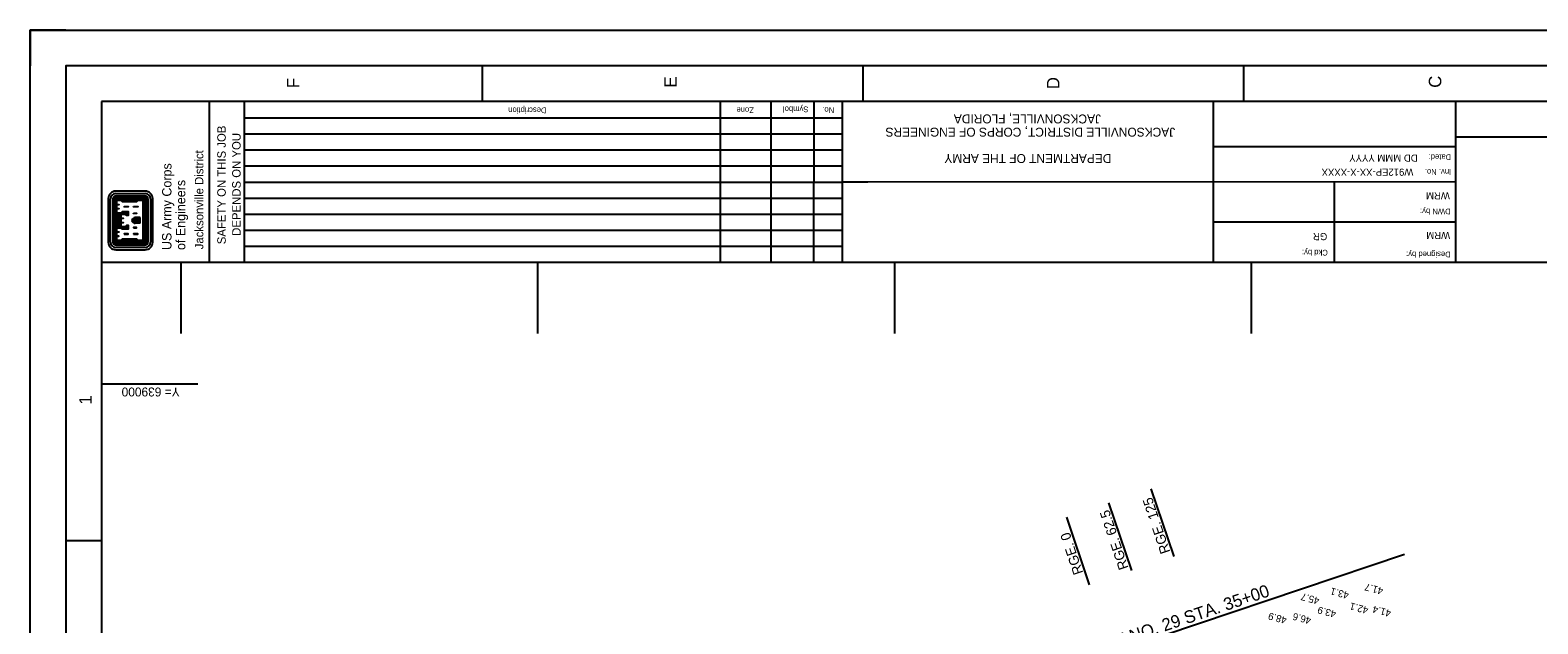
# Model space of a CAD drawing. Extents: x 945289 to 948688, y 635096 to 639496.
# Drawn here: x 945289 to 947401, y 638664 to 639496 of the extents above; entities that cross this region are included whole.
import ezdxf

# ---------------------------------------------------------------- set-up
doc = ezdxf.new("R2010")
doc.units = 0
for name, color, linetype in [('G-ANNO-NPLT', 7, 'Continuous'), ('G-ANNO-TEXT-DRWG', 7, 'Continuous'), ('G-ANNO-TEXT-LOGO', 7, 'Continuous'), ('G-ANNO-TEXT-PROJ', 7, 'Continuous'), ('G-ANNO-TEXT-TTLB', 7, 'Continuous'), ('G-ANNO-TTLB', 7, 'Continuous'), ('V-ALGN-TEXT', 7, 'Continuous'), ('V-ANNO-MATC', 7, 'Continuous'), ('V-ANNO-MATC-IDEN', 7, 'Continuous'), ('V-TOPO-COOR-STAT', 7, 'Continuous'), ('V-TOPO-SOUN', 7, 'Continuous')]:
    doc.layers.add(name, color=color, linetype=linetype)

msp = doc.modelspace()

# ---------------------------------------------------------------- linework, layer by layer
at = {"layer": 'G-ANNO-NPLT'}
msp.add_lwpolyline([(945288.5, 635095.9), (945288.5, 639495.8), (948688.5, 639495.8), (948688.5, 635095.9)], close=True, dxfattribs=at)
msp.add_lwpolyline([(945338.5, 639495.8), (945288.5, 639495.8), (945288.5, 639445.8)], dxfattribs=at)
at = {"layer": 'G-ANNO-TEXT-LOGO'}
for p, q in [((945397.9, 639259.7), (945397.9, 639198.9)), ((945401.1, 639198.9), (945401.1, 639259.7)), ((945404.5, 639259.7), (945404.5, 639198.9)), ((945405.4, 639259.7), (945405.4, 639198.9)), ((945406.3, 639259.7), (945406.3, 639198.9)), ((945407.1, 639259.7), (945407.1, 639198.9)), ((945408, 639259.7), (945408, 639198.9)), ((945449.6, 639270.4), (945408.6, 639270.4)), ((945408.6, 639267.1), (945449.6, 639267.1)), ((945408.6, 639263.7), (945449.6, 639263.7)), ((945408.6, 639262.8), (945449.6, 639262.8)), ((945408.6, 639261.9), (945449.6, 639261.9)), ((945408.6, 639261.1), (945449.6, 639261.1)), ((945408.6, 639260.2), (945449.6, 639260.2)), ((945408.6, 639259.3), (945449.3, 639259.3)), ((945408.6, 639258.5), (945448.4, 639258.5)), ((945417.4, 639257.8), (945438.2, 639257.8)), ((945418.2, 639256.9), (945437.3, 639256.9)), ((945448.4, 639258.5), (945448.4, 639200.1)), ((945449.3, 639259.3), (945449.3, 639199.3)), ((945450.2, 639259.7), (945450.2, 639198.9)), ((945451, 639259.7), (945451, 639198.9)), ((945451.9, 639259.7), (945451.9, 639198.9)), ((945452.8, 639259.7), (945452.8, 639198.9)), ((945453.6, 639259.7), (945453.6, 639198.9)), ((945457.1, 639259.7), (945457.1, 639198.9)), ((945460.4, 639198.9), (945460.4, 639259.7)), ((945408.8, 639220), (945408.8, 639238.6)), ((945409.7, 639220), (945409.7, 639238.6)), ((945410.5, 639220), (945410.5, 639238.6)), ((945411.4, 639220), (945411.4, 639238.6)), ((945412.3, 639220), (945412.3, 639238.6)), ((945413.1, 639220), (945413.1, 639238.6)), ((945414, 639220), (945414, 639238.6)), ((945442.5, 639233.3), (945435.8, 639233.3)), ((945442.5, 639232.5), (945435.8, 639232.5)), ((945442.5, 639231.6), (945435.8, 639231.6)), ((945442.5, 639230.7), (945435.8, 639230.7)), ((945442.5, 639229.9), (945435.8, 639229.9)), ((945442.5, 639228.7), (945435.8, 639228.7)), ((945442.5, 639227.9), (945435.8, 639227.9)), ((945442.5, 639227), (945435.8, 639227)), ((945442.5, 639226.1), (945435.8, 639226.1)), ((945442.5, 639225.3), (945435.8, 639225.3)), ((945442.5, 639225.3), (945442.5, 639233.3)), ((945408.6, 639200.1), (945448.4, 639200.1)), ((945408.6, 639199.3), (945449.3, 639199.3)), ((945408.6, 639198.4), (945449.6, 639198.4)), ((945408.6, 639197.5), (945449.6, 639197.5)), ((945408.6, 639196.6), (945449.6, 639196.6)), ((945408.6, 639195.8), (945449.6, 639195.8)), ((945408.6, 639194.9), (945449.6, 639194.9)), ((945417.3, 639200.8), (945438.3, 639200.8)), ((945418.2, 639201.7), (945437.3, 639201.7)), ((945449.6, 639191.4), (945408.6, 639191.4)), ((945408.6, 639188.2), (945449.6, 639188.2))]:
    msp.add_line(p, q, dxfattribs=at)
for points in [[(945408.6, 639200.8), (945416.5, 639200.8), (945418.2, 639202.5), (945437.3, 639202.5), (945439.1, 639200.8), (945447.8, 639200.8), (945447.8, 639257.8), (945439.1, 639257.8), (945437.3, 639256), (945418.2, 639256), (945416.5, 639257.8), (945408.6, 639257.8), (945408.6, 639250.3), (945408.6, 639244.5), (945408.6, 639239.1), (945416.5, 639239.1), (945418.2, 639241), (945425.2, 639241), (945425.2, 639236.8), (945424.5, 639236.8), (945422.7, 639238.6), (945414.9, 639238.6), (945414.9, 639231.1), (945414.9, 639225.3), (945414.9, 639220), (945422.7, 639220), (945424.5, 639221.8), (945425.2, 639221.8), (945425.2, 639217.6), (945418.2, 639217.6), (945416.5, 639219.4), (945408.6, 639219.4), (945408.6, 639211.9), (945408.6, 639206.1), (945408.6, 639200.8)], [(945409.5, 639201.6), (945416.1, 639201.6), (945417.9, 639203.4), (945437.7, 639203.4), (945439.5, 639201.6), (945446.9, 639201.6), (945446.9, 639257), (945439.5, 639257), (945437.7, 639255.1), (945417.9, 639255.1), (945416.1, 639257), (945409.5, 639257), (945409.5, 639251.6), (945412.6, 639251.6), (945412.6, 639251.1), (945409.5, 639251.1), (945409.5, 639245.8), (945412.6, 639245.8), (945412.6, 639245.4), (945409.5, 639245.4), (945409.5, 639240), (945416.1, 639240), (945417.9, 639241.8), (945426, 639241.8), (945426, 639236), (945424.1, 639236), (945422.3, 639237.8), (945415.7, 639237.8), (945415.7, 639232.4), (945418.8, 639232.4), (945418.8, 639232), (945415.7, 639232), (945415.7, 639226.6), (945418.8, 639226.6), (945418.8, 639226.1), (945415.7, 639226.1), (945415.7, 639220.8), (945422.3, 639220.8), (945424.1, 639222.6), (945426, 639222.6), (945426, 639216.8), (945417.9, 639216.8), (945416.1, 639218.6), (945409.5, 639218.6), (945409.5, 639213.3), (945412.6, 639213.3), (945412.6, 639212.8), (945409.5, 639212.8), (945409.5, 639207.4), (945412.6, 639207.4), (945412.6, 639207), (945409.5, 639207), (945409.5, 639201.6)], [(945418.1, 639239.6), (945418.6, 639240.1), (945424.3, 639240.1), (945424.3, 639238.3), (945423, 639239.5), (945418, 639239.5)], [(945420.2, 639248.7), (945426, 639248.7), (945426, 639248.2), (945420.2, 639248.2), (945420.2, 639248.7)], [(945433.5, 639248.7), (945439.4, 639248.7), (945439.4, 639248.2), (945433.5, 639248.2), (945433.5, 639248.7)], [(945433.5, 639239.6), (945437.6, 639239.6), (945437.6, 639239.1), (945433.5, 639239.1), (945433.5, 639239.6)], [(945418.1, 639219), (945418.6, 639218.5), (945424.3, 639218.5), (945424.3, 639220.4), (945423, 639219.1), (945418, 639219.1)], [(945433.5, 639219), (945437.6, 639219), (945437.6, 639219.5), (945433.5, 639219.5), (945433.5, 639219)], [(945420.2, 639209.8), (945426, 639209.8), (945426, 639210.4), (945420.2, 639210.4), (945420.2, 639209.8)], [(945433.5, 639209.8), (945439.4, 639209.8), (945439.4, 639210.4), (945433.5, 639210.4), (945433.5, 639209.8)]]:
    msp.add_lwpolyline(points, dxfattribs=at)
for centre, major_axis, start_param, end_param in [((945408.6, 639259.6), (0, 10.7), 6.283169, 7.853965), ((945408.6, 639259.6), (0, 7.49), 6.28317, 7.853966), ((945408.6, 639259.6), (0, 4.02), 6.283169, 7.853965), ((945408.6, 639259.6), (0, 3.15), 6.283169, 7.853965), ((945408.6, 639259.6), (0, 2.28), 6.283169, 7.853965), ((945408.6, 639259.6), (0, 1.41), 6.283169, 7.853965), ((945408.6, 639259.6), (0, 0.546), 6.283169, 7.853965), ((945449.6, 639259.6), (0, 10.7), 4.712373, 6.28317), ((945449.6, 639259.6), (0, -7.49), 1.570781, 3.141577), ((945449.6, 639259.6), (0, 4.02), 4.712373, 6.28317), ((945449.6, 639259.6), (0, 3.15), 4.712373, 6.28317), ((945449.6, 639259.6), (0, 2.28), 4.712373, 6.28317), ((945449.6, 639259.6), (0, 1.41), 4.712373, 6.28317), ((945449.6, 639259.6), (0, 0.546), 4.712373, 6.28317), ((945436.2, 639227.8), (0, 5.55), 0.068795, 1.29842), ((945436.2, 639230.8), (0, -5.55), 4.985832, 6.214359), ((945436.2, 639227.8), (0, 4.69), 0.068795, 1.335689), ((945436.2, 639230.8), (0, -4.69), 4.947465, 6.21436), ((945436.2, 639227.8), (0, 3.82), 0.068795, 1.335689), ((945436.2, 639230.8), (0, -3.82), 4.947465, 6.21436), ((945436.2, 639227.8), (0, 2.95), 0.068794, 1.335689), ((945436.2, 639230.8), (0, -2.95), 4.947465, 6.21436), ((945436.2, 639230.8), (0, -2.08), 4.947465, 6.214359), ((945436.2, 639227.8), (0, 2.08), 0.068794, 1.335689), ((945408.6, 639198.9), (0, 10.7), 1.57078, 3.141576), ((945408.6, 639198.9), (0, 7.49), 1.57078, 3.141576), ((945408.6, 639198.9), (0, 4.02), 1.57078, 3.141576), ((945408.6, 639198.9), (0, 3.15), 1.57078, 3.141576), ((945408.6, 639198.9), (0, 2.28), 1.57078, 3.141576), ((945408.6, 639198.9), (0, 1.41), 1.57078, 3.141576), ((945408.6, 639198.9), (0, 0.546), 1.57078, 3.141576), ((945449.6, 639198.9), (0, -4.02), 6.28317, 7.853966), ((945449.6, 639198.9), (0, -3.15), 6.28317, 7.853966), ((945449.6, 639198.9), (0, -2.28), 6.28317, 7.853966), ((945449.6, 639198.9), (0, -1.41), 6.28317, 7.853966), ((945449.6, 639198.9), (0, -0.546), 6.28317, 7.853966), ((945449.6, 639198.9), (0, -10.7), 6.28317, 7.853966), ((945449.6, 639198.9), (0, -7.49), 6.28317, 7.853966)]:
    msp.add_ellipse(centre, major_axis=major_axis, ratio=0.99964, start_param=start_param, end_param=end_param, dxfattribs=at)
at = {"layer": 'G-ANNO-TTLB'}
for p, q in [((945922, 639445.8), (945922, 639395.8)), ((946455.3, 639445.8), (946455.3, 639395.8)), ((946988.6, 639445.8), (946988.6, 639395.8)), ((945539.7, 639170.8), (945539.7, 639395.8)), ((945588.9, 639170.2), (945588.9, 639395.2)), ((946255.7, 639170.8), (946255.7, 639395.8)), ((946326.9, 639170.8), (946326.9, 639395.8)), ((946386.9, 639170.8), (946387, 639395.8)), ((946426.8, 639170.8), (946426.8, 639395.8)), ((946946.7, 639170), (946946.7, 639395.8)), ((947286.3, 639169.6), (947286.3, 639395.8)), ((945588.9, 639373.1), (946426.8, 639373.1)), ((945588.9, 639350.6), (946426.8, 639350.6)), ((947286.3, 639346.5), (947637.7, 639346.5)), ((945588.9, 639328.1), (946426.8, 639328.1)), ((946946.7, 639332.9), (947286.3, 639332.9)), ((945588.9, 639305.6), (946426.8, 639305.6)), ((945588.9, 639283.1), (946426.8, 639283.1)), ((947286.3, 639282.7), (946426.8, 639283.3)), ((946426.8, 639283.3), (946462.2, 639283.3)), ((947116.5, 639170), (947116.5, 639282.8)), ((945588.9, 639260.6), (946426.8, 639260.6)), ((945588.9, 639238.1), (946426.8, 639238.1)), ((945588.9, 639215.6), (946426.8, 639215.6)), ((947286.3, 639226.7), (946946.7, 639227)), ((945588.9, 639193.1), (946426.8, 639193.1)), ((945388.5, 639170.8), (948588.5, 639170.8)), ((945338.5, 638780.8), (945388.5, 638780.8))]:
    msp.add_line(p, q, dxfattribs=at)
for points in [[(948638.5, 635145.9), (948638.5, 639445.8), (945338.5, 639445.8), (945338.5, 635145.9)], [(945388.5, 639395.8), (945388.5, 635270.9), (948588.5, 635270.9), (948588.5, 639395.8)]]:
    msp.add_lwpolyline(points, close=True, dxfattribs=at)
at = {"layer": 'V-ALGN-TEXT'}
for p, q in [((946832.1, 638738.7), (946800.3, 638833.5)), ((946891.4, 638758.6), (946859.6, 638853.4)), ((946772.8, 638718.9), (946741, 638813.7))]:
    msp.add_line(p, q, dxfattribs=at)
at = {"layer": 'V-ANNO-MATC'}
msp.add_line((946610.8, 638559.1), (947214.6, 638761.5), dxfattribs=at)
at = {"layer": 'V-TOPO-COOR-STAT'}
for p, q in [((945500, 639070.8), (945500, 639170.8)), ((946000, 639070.8), (946000, 639170.8)), ((946500, 639070.8), (946500, 639170.8)), ((947000, 639070.8), (947000, 639170.8)), ((945523.5, 639000), (945388.5, 639000))]:
    msp.add_line(p, q, dxfattribs=at)

# ---------------------------------------------------------------- texts
at = {"layer": 'G-ANNO-TEXT-DRWG'}
for s, p in [('WRM', (947278, 639268.7)), ('GR', (947106.2, 639211.6)), ('WRM', (947278.3, 639213.1))]:
    msp.add_text(s, height=10, rotation=180, dxfattribs=at).set_placement(p)
at = {"layer": 'G-ANNO-TEXT-PROJ'}
for s, p in [('DD MMM YYYY', (947232.8, 639321.6)), ('W912EP-XX-X-XXXX', (947226.8, 639301.8))]:
    msp.add_text(s, height=10, rotation=180, dxfattribs=at).set_placement(p)
at = {"layer": 'G-ANNO-TEXT-TTLB'}
for s, height, rotation, p in [('Description', 8, 180, (946012, 639387.5)), ('Zone', 8, 180, (946302.7, 639387.8)), ('Symbol', 8, 180, (946379.1, 639388.9)), ('No.', 8, 180, (946415.2, 639387.9)), ('SAFETY ON THIS JOB', 11.9, 90, (945562.6, 639195.9)), ('JACKSONVILLE DISTRICT, CORPS OF ENGINEERS', 12.5, 180, (946893, 639359.2)), ('JACKSONVILLE, FLORIDA', 12.5, 180, (946789.1, 639377.7)), ('DEPENDS ON YOU', 11.9, 90, (945583.5, 639207.7)), ('Jacksonville District', 11.9, 90, (945531.2, 639188.8)), ('DEPARTMENT OF THE ARMY', 12.5, 180, (946803.6, 639322.2)), ('Dated:', 8, 180, (947279.7, 639321.9)), ('US Army Corps', 13.086, 90, (945486.5, 639187.8)), ('Inv. No.', 8, 180, (947279.8, 639301.1)), ('of Engineers', 13.086, 90, (945505.9, 639187.8)), ('DWN by:', 8, 180, (947279, 639245.9)), ('Ckd by:', 8, 180, (947107, 639188.1)), ('Designed by:', 8, 180, (947279.1, 639185.6))]:
    msp.add_text(s, height=height, rotation=rotation, dxfattribs=at).set_placement(p)
at = {"layer": 'G-ANNO-TTLB'}
for s, p in [('F', (945665.8, 639414.6)), ('E', (946194.7, 639415.4)), ('D', (946730.8, 639413.2)), ('C', (947266, 639415.1)), ('1', (945374.7, 638971.2))]:
    msp.add_text(s, height=17.5, rotation=90, dxfattribs=at).set_placement(p)
at = {"layer": 'V-ALGN-TEXT'}
for s, p in [('RGE. 125', (946886.3, 638765)), ('RGE. 62.5', (946827.9, 638742.6)), ('RGE. 0', (946764.3, 638735.6))]:
    msp.add_text(s, height=13.92, rotation=108.5381, dxfattribs=at).set_placement(p)
at = {"layer": 'V-ANNO-MATC-IDEN'}
msp.add_text('MATCHLINE SHEET NO. 29 STA. 35+00', height=17.52, rotation=18.5381, dxfattribs=at).set_placement((946617.5, 638565.9))
at = {"layer": 'V-TOPO-COOR-STAT'}
msp.add_text('Y= 639000', height=12.5, rotation=180, dxfattribs=at).set_placement((945498, 638995.2))
at = {"layer": 'V-TOPO-SOUN'}
for s, p in [('45.7 ', (947095.9, 638700.6)), ('43.1 ', (947137.3, 638708.2)), ('41.7 ', (947185.3, 638714.3)), ('43.9 ', (947119.3, 638681.9)), ('42.1 ', (947164.4, 638687.3)), ('41.4 ', (947196.4, 638683.1)), ('48.9 ', (947050.2, 638673.4)), ('46.6 ', (947084.4, 638672.9))]:
    msp.add_text(s, height=10, rotation=165, dxfattribs=at).set_placement(p)

doc.saveas('drawing.dxf')
